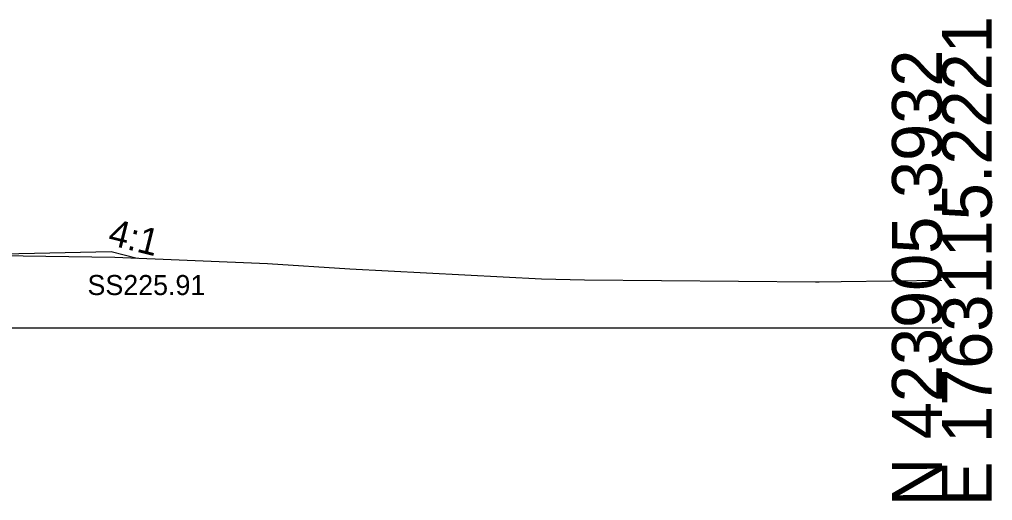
# Model space of a CAD drawing. Extents: x -26 to 3203, y -11010 to 4024.
# Drawn here: x 1148.3 to 1202.8, y 2490.3 to 2517.3 of the extents above; entities that cross this region are included whole.
import ezdxf

# ---------------------------------------------------------------- set-up
doc = ezdxf.new("R2010")
doc.units = 0
for name, color, linetype in [('Exist Cross Section Cell', 7, 'Continuous'), ('Exist XS Ground Line', 7, 'Continuous'), ('Prop CMT Slope Grass', 7, 'Continuous'), ('Prop XS Side Slope Text', 7, 'Continuous'), ('Prop XS SS Elevation Text', 7, 'Continuous'), ('Scratch_Level_0', 7, 'Continuous')]:
    doc.layers.add(name, color=color, linetype=linetype)

msp = doc.modelspace()

# ---------------------------------------------------------------- linework, layer by layer
at = {"layer": 'Exist Cross Section Cell'}
msp.add_line((1100, 2500), (1200, 2500), dxfattribs=at)
at = {"layer": 'Exist XS Ground Line'}
msp.add_lwpolyline([(1144.577, 2504.096), (1153.62, 2503.961), (1162.178, 2503.599), (1166.788, 2503.315), (1177.549, 2502.745), (1179.956, 2502.684), (1192.919, 2502.573), (1193.124, 2502.57), (1194.346, 2502.589), (1200, 2502.669)], dxfattribs=at)
msp.add_lwpolyline([(1144.577, 2504.096), (1153.62, 2503.961), (1162.178, 2503.599), (1166.788, 2503.315), (1177.549, 2502.745), (1179.956, 2502.684), (1192.919, 2502.573), (1193.124, 2502.57), (1194.346, 2502.589), (1200, 2502.669)], dxfattribs=at)
msp.add_lwpolyline([(1144.577, 2504.096), (1153.62, 2503.961), (1162.178, 2503.599), (1166.788, 2503.315), (1177.549, 2502.745), (1179.956, 2502.684), (1192.919, 2502.573), (1193.124, 2502.57), (1194.346, 2502.589), (1200, 2502.669)], dxfattribs=at)
msp.add_lwpolyline([(1144.577, 2504.096), (1153.62, 2503.961), (1162.178, 2503.599), (1166.788, 2503.315), (1177.549, 2502.745), (1179.956, 2502.684), (1192.919, 2502.573), (1193.124, 2502.57), (1194.346, 2502.589), (1200, 2502.669)], dxfattribs=at)
msp.add_lwpolyline([(1144.577, 2504.096), (1153.62, 2503.961), (1162.178, 2503.599), (1166.788, 2503.315), (1177.549, 2502.745), (1179.956, 2502.684), (1192.919, 2502.573), (1193.124, 2502.57), (1194.346, 2502.589), (1200, 2502.669)], dxfattribs=at)
at = {"layer": 'Prop CMT Slope Grass'}
msp.add_lwpolyline([(1143.91, 2504.083), (1153.41, 2504.273), (1154.869, 2503.908)], dxfattribs=at)

# ---------------------------------------------------------------- texts
at = {"layer": 'Exist Cross Section Cell'}
for s, p in [('E 1763115.2221', (1202.8, 2490)), ('N 423905.3932', (1200, 2490))]:
    msp.add_text(s, height=2.8, rotation=90, dxfattribs=at).set_placement(p)
at = {"layer": 'Prop XS Side Slope Text'}
msp.add_text('4:1', height=1.5, rotation=345.9638, dxfattribs=at).set_placement((1153.158, 2504.686))
at = {"layer": 'Prop XS SS Elevation Text'}
msp.add_text('SS225.91', height=1.125, dxfattribs=at).set_placement((1152.08, 2501.837))
at = {"layer": 'Scratch_Level_0'}
for s, p in [('RT_CSLP_Pnt', (1153.311, 2504.263)), ('Exterior Boundary', (1154.711, 2503.898)), ('RT_Slope_Fill', (1154.775, 2503.898))]:
    msp.add_text(s, height=0.02, dxfattribs=at).set_placement(p)

doc.saveas('drawing.dxf')
